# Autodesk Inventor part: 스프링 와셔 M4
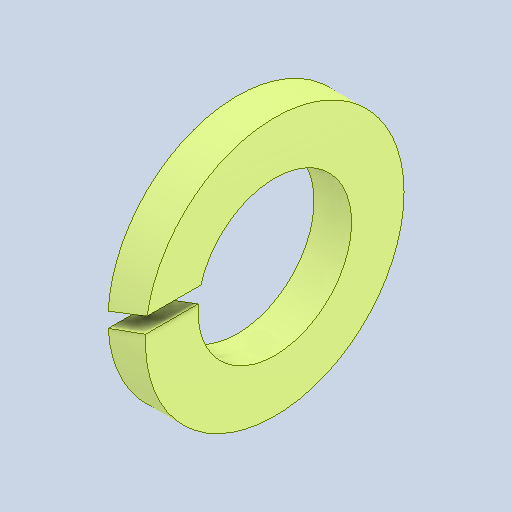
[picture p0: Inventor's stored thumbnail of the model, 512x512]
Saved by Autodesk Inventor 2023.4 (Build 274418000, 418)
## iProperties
Created: 2024-05
Part Number: 스프링 와셔 M4
Material: 강철, 연강
Description: 스프링 잠금 와셔
Document SubType Name: Modeling
Designer: edu-40
Density: 7.85 g/cm^3
Appearance: 기본값
Author: jhkim
Sending System: Autodesk Inventor 2025
Preprocessor: ST-DEVELOPER v20
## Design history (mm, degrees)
feature "Solid1"
node "솔리드1"
